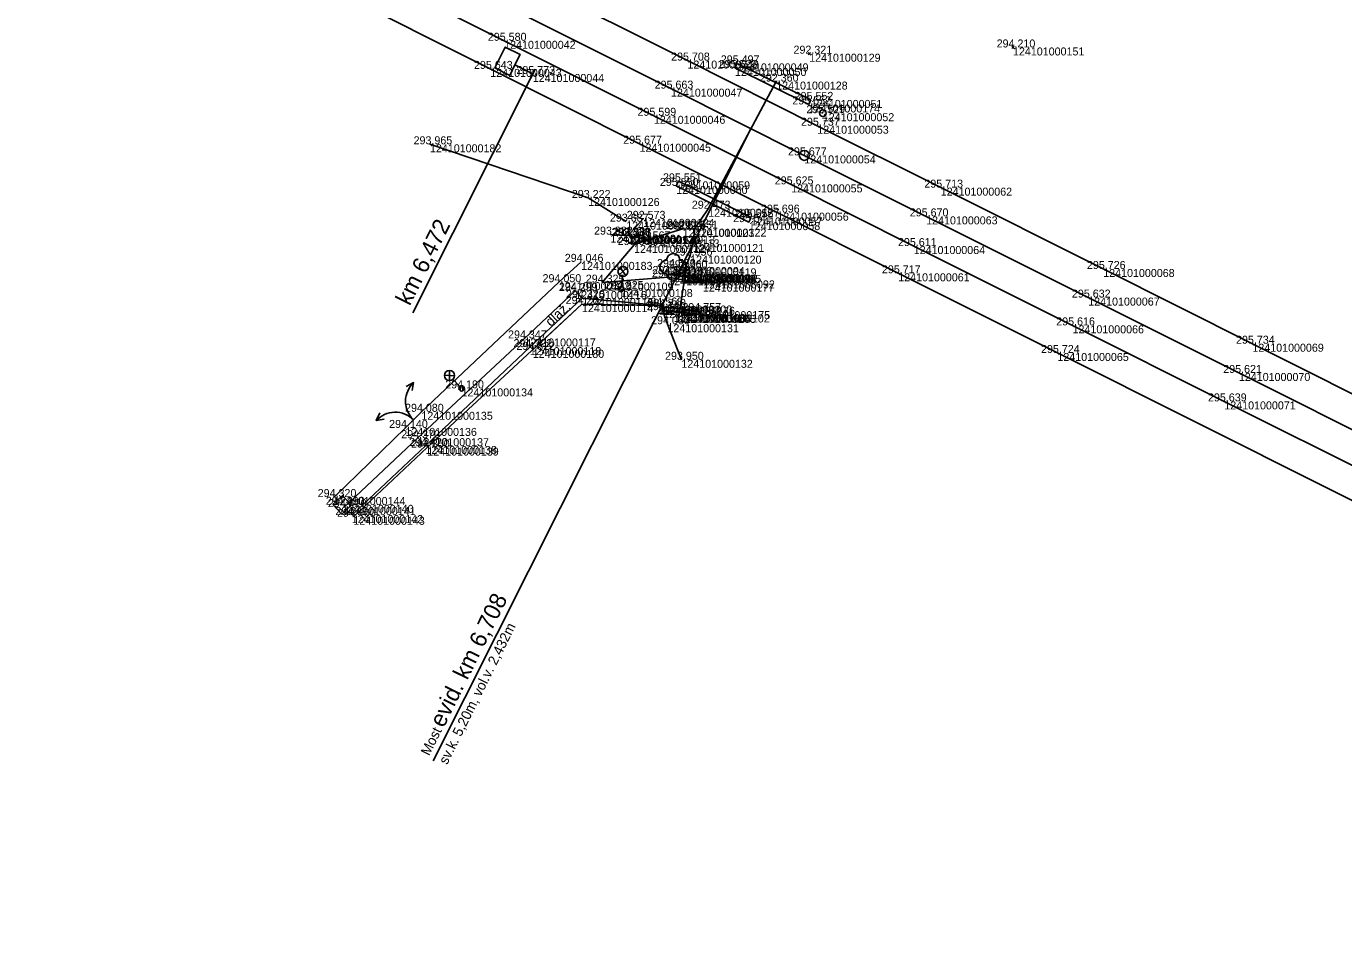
# Model space of a CAD drawing. Extents: x -616949 to -607976, y -1164436 to -1159224.
# Drawn here: x -613176.1 to -612978.5, y -1161728 to -1161592 of the extents above; entities that cross this region are included whole.
import ezdxf

# ---------------------------------------------------------------- set-up
doc = ezdxf.new("R2010")
doc.units = 0
for name, color, linetype in [('Vrstva 1', 7, 'Continuous'), ('Vrstva 16', 7, 'Continuous'), ('Vrstva 17', 7, 'Continuous'), ('Vrstva 18', 7, 'Continuous'), ('Vrstva 19', 7, 'Continuous'), ('Vrstva 25', 7, 'Continuous'), ('Vrstva 47', 7, 'Continuous'), ('Vrstva 49', 7, 'Continuous'), ('Vrstva 50', 7, 'Continuous'), ('Vrstva 51', 7, 'Continuous'), ('Vrstva 60', 7, 'Continuous'), ('Vrstva 61', 7, 'Continuous'), ('Vrstva 7', 7, 'Continuous')]:
    doc.layers.add(name, color=color, linetype=linetype)

msp = doc.modelspace()

# ---------------------------------------------------------------- linework, layer by layer
at = {"layer": 'Vrstva 1'}
for points in [[(-612836.3, -1161723.7), (-612837.64, -1161723.01), (-612851, -1161716.12), (-612864.8, -1161706.96), (-612874.11, -1161700.74), (-612883.8, -1161694.67), (-612893.99, -1161688.92), (-612900.94, -1161685.35), (-612902.32, -1161684.67), (-612923.96, -1161673.82), (-612946.7, -1161662.43), (-612968.71, -1161651.4), (-612992.18, -1161639.63), (-613014.55, -1161628.42), (-613038.93, -1161616.22), (-613057.44, -1161606.93), (-613076.92, -1161597.16), (-613100.26, -1161585.47), (-613122.66, -1161574.25), (-613146.78, -1161562.2), (-613166.98, -1161552.11), (-613189.63, -1161540.79)], [(-612836.3, -1161723.7), (-612837.64, -1161723.01), (-612851, -1161716.12), (-612865.7, -1161708.54), (-612879.87, -1161701.29), (-612896.11, -1161693.08), (-612897.16, -1161692.56), (-612899.6, -1161691.36), (-612902.62, -1161689.84), (-612904.01, -1161689.16), (-612926.34, -1161677.97), (-612949.01, -1161666.64), (-612970.85, -1161655.69), (-612994.2, -1161644.02), (-613016.8, -1161632.71), (-613041.11, -1161620.53), (-613059.39, -1161611.38), (-613079.39, -1161601.37), (-613102.4, -1161589.86), (-613124.84, -1161578.63), (-613149.33, -1161566.38), (-613169.01, -1161556.54), (-613191.83, -1161545.12)], [(-612838.4, -1161727.97), (-612839.52, -1161727.39), (-612849.62, -1161722.19), (-612861.87, -1161715.89), (-612876.82, -1161708.21), (-612890.37, -1161701.36), (-612894.8, -1161699.12), (-612896.29, -1161698.37), (-612899.37, -1161696.83), (-612901.81, -1161695.62), (-612928.78, -1161682.13), (-612951.31, -1161670.85), (-612973.15, -1161659.9), (-612996.39, -1161648.28), (-613019.15, -1161636.88), (-613042.98, -1161624.98), (-613061.36, -1161615.73), (-613081.95, -1161605.44), (-613104.41, -1161594.19), (-613127.64, -1161582.55), (-613152.33, -1161570.2), (-613170.83, -1161560.95), (-613193.86, -1161549.42)], [(-612838.4, -1161727.97), (-612839.52, -1161727.39), (-612849.62, -1161722.19), (-612862.62, -1161717.56), (-612874.04, -1161713.43), (-612884.82, -1161709.14), (-612890.21, -1161706.69), (-612892.64, -1161705.54), (-612895.15, -1161704.3), (-612918.74, -1161692.45), (-613021.43, -1161641.02), (-613045.3, -1161629.07), (-613063.44, -1161619.97), (-613084.1, -1161609.63), (-613106.49, -1161598.41), (-613129.98, -1161586.61), (-613154.55, -1161574.23)]]:
    msp.add_lwpolyline(points, dxfattribs=at)
at = {"layer": 'Vrstva 16'}
for points in [[(-613128.4, -1161664.14), (-613117.4, -1161653.8), (-613101.38, -1161638.84)], [(-613100.56, -1161640.14), (-613116.22, -1161654.97), (-613127.28, -1161665.33)]]:
    msp.add_lwpolyline(points, dxfattribs=at)
at = {"layer": 'Vrstva 17'}
for p, q in [((-613092.87, -1161627.35), (-613096.2, -1161630.4)), ((-613096.2, -1161630.4), (-613116.83, -1161649.84)), ((-613100.12, -1161640.55), (-613092.74, -1161633.68)), ((-613092.74, -1161633.68), (-613080.92, -1161633.9)), ((-613080.92, -1161633.9), (-613079.92, -1161636.71)), ((-613079.92, -1161636.71), (-613077.83, -1161642.04)), ((-613116.83, -1161649.84), (-613119.22, -1161652.26)), ((-613119.22, -1161652.26), (-613129.93, -1161662.63))]:
    msp.add_line(p, q, dxfattribs=at)
for points in [[(-613127.03, -1161665.59), (-613115.94, -1161655.21), (-613092.74, -1161633.68)], [(-613119.12, -1161646.04), (-613117.99, -1161645.46), (-613118.19, -1161646.67)], [(-613123.05, -1161650.02), (-613123.61, -1161651.16), (-613122.41, -1161650.94)]]:
    msp.add_lwpolyline(points, dxfattribs=at)
for centre, start, end in [((-613115.38, -1161648.27), 132.8722, 226.3921), ((-613120.77, -1161653.73), 44.3226, 137.8425)]:
    msp.add_arc(centre, 3.83, start, end, dxfattribs=at)
at = {"layer": 'Vrstva 18'}
for p, q in [((-613058.73, -1161603.74), (-613069.79, -1161598.27)), ((-613058.73, -1161603.74), (-613058.39, -1161603.06)), ((-613067.39, -1161607.38), (-613115.05, -1161702.21))]:
    msp.add_line(p, q, dxfattribs=at)
for points in [[(-613069.79, -1161598.27), (-613069.47, -1161597.58), (-613058.39, -1161603.06)], [(-613067.37, -1161620.69), (-613078.24, -1161615.27), (-613078.61, -1161615.96), (-613067.71, -1161621.39), (-613067.37, -1161620.69)]]:
    msp.add_lwpolyline(points, dxfattribs=at)
at = {"layer": 'Vrstva 19'}
for p, q in [((-613063.6, -1161600.31), (-613073.81, -1161619.38)), ((-613079.8, -1161629.67), (-613079.71, -1161629.18)), ((-613074.61, -1161630.62), (-613079.8, -1161629.67)), ((-613074.52, -1161630.13), (-613079.71, -1161629.18)), ((-613078.15, -1161629.2), (-613079.71, -1161629.18)), ((-613078.16, -1161635.26), (-613077.24, -1161629.26)), ((-613074.52, -1161630.13), (-613076.57, -1161629.3)), ((-613074.61, -1161630.62), (-613074.52, -1161630.13)), ((-613080.56, -1161634.59), (-613080.5, -1161634.1)), ((-613075.29, -1161635.24), (-613080.56, -1161634.59)), ((-613080.56, -1161634.59), (-613078.94, -1161635.16)), ((-613075.23, -1161634.74), (-613080.5, -1161634.1)), ((-613077.34, -1161635.31), (-613075.29, -1161635.24)), ((-613075.29, -1161635.24), (-613075.23, -1161634.74))]:
    msp.add_line(p, q, dxfattribs=at)
at = {"layer": 'Vrstva 25'}
for p, q in [((-613087.14, -1161629.3), (-613086.04, -1161628.28)), ((-613087.03, -1161628.19), (-613086.14, -1161629.39)), ((-613086.66, -1161629.54), (-613086.8, -1161631.03)), ((-613087.23, -1161631.47), (-613086.72, -1161631.05)), ((-613087, -1161631.79), (-613086.45, -1161631.34)), ((-613112.6, -1161645.15), (-613112.63, -1161643.65)), ((-613113.36, -1161644.33), (-613111.86, -1161644.46)), ((-613112.1, -1161644.94), (-613111.07, -1161646.04)), ((-613111.03, -1161646.65), (-613111.01, -1161645.99)), ((-613110.63, -1161646.69), (-613110.61, -1161645.98))]:
    msp.add_line(p, q, dxfattribs=at)
for centre, radius in [((-613086.59, -1161628.79), 0.749), ((-613086.84, -1161631.43), 0.4), ((-613112.61, -1161644.4), 0.749), ((-613110.8, -1161646.33), 0.4)]:
    msp.add_circle(centre, radius, dxfattribs=at)
at = {"layer": 'Vrstva 47'}
msp.add_lwpolyline([(-613130.12, -1161663.75), (-613128.67, -1161662.38), (-613127.3, -1161663.83), (-613128.75, -1161665.2), (-613130.12, -1161663.75)], dxfattribs=at)
at = {"layer": 'Vrstva 49'}
for p, q in [((-613058.83, -1161595.95), (-613058.48, -1161596.31)), ((-613058.83, -1161596.31), (-613058.48, -1161595.95)), ((-613028.27, -1161595.01), (-613027.91, -1161595.37)), ((-613028.27, -1161595.37), (-613027.91, -1161595.01)), ((-613085.8, -1161623.42), (-613083.57, -1161620.9)), ((-613088.48, -1161623.27), (-613085.68, -1161623.47)), ((-613085.68, -1161623.47), (-613082.82, -1161623.98)), ((-613082.82, -1161623.98), (-613077.62, -1161622.4)), ((-613079.8, -1161629.67), (-613089.72, -1161630.47))]:
    msp.add_line(p, q, dxfattribs=at)
for points in [[(-613086.1, -1161621.32), (-613091.81, -1161617.77), (-613115.54, -1161609.72)], [(-613077.24, -1161629.26), (-613077.27, -1161628.32), (-613076.52, -1161626.42), (-613076.13, -1161624.67), (-613075.79, -1161622.37), (-613073.81, -1161619.38)], [(-613089.72, -1161630.47), (-613084.93, -1161624.82), (-613082.82, -1161623.98)]]:
    msp.add_lwpolyline(points, dxfattribs=at)
at = {"layer": 'Vrstva 50'}
msp.add_line((-613079.1, -1161628.13), (-613078.96, -1161628.13), dxfattribs=at)
for centre, start, end in [((-613080.04, -1161628.12), 90, 270), ((-613079.04, -1161627.12), 0, 180), ((-613078.04, -1161628.12), 270, 90), ((-613079.04, -1161629.12), 180, 0)]:
    msp.add_arc(centre, 1, start, end, dxfattribs=at)
at = {"layer": 'Vrstva 51'}
msp.add_line((-613089.72, -1161630.47), (-613079.8, -1161629.67), dxfattribs=at)
for points in [[(-613101.38, -1161638.84), (-613093.75, -1161631.72), (-613092.7, -1161632.78), (-613100.56, -1161640.14)], [(-613092.7, -1161632.78), (-613080.92, -1161633.9), (-613080.5, -1161634.1)]]:
    msp.add_lwpolyline(points, dxfattribs=at)
at = {"layer": 'Vrstva 60'}
for p, q in [((-613104.41, -1161594.19), (-613104.41, -1161594.19)), ((-613058.66, -1161596.13), (-613058.66, -1161596.13)), ((-613028.09, -1161595.19), (-613028.09, -1161595.19)), ((-613076.92, -1161597.16), (-613076.92, -1161597.16)), ((-613069.79, -1161598.27), (-613069.79, -1161598.27)), ((-613069.47, -1161597.58), (-613069.47, -1161597.58)), ((-613106.49, -1161598.41), (-613106.49, -1161598.41)), ((-613100.12, -1161599.17), (-613100.12, -1161599.17)), ((-613079.39, -1161601.37), (-613079.39, -1161601.37)), ((-613063.6, -1161600.31), (-613063.6, -1161600.31)), ((-613058.73, -1161603.74), (-613058.73, -1161603.74)), ((-613058.39, -1161603.06), (-613058.39, -1161603.06)), ((-613081.95, -1161605.44), (-613081.95, -1161605.44)), ((-613056.61, -1161605.05), (-613056.61, -1161605.05)), ((-613057.44, -1161606.93), (-613057.44, -1161606.93)), ((-613115.54, -1161609.72), (-613115.54, -1161609.72)), ((-613084.1, -1161609.63), (-613084.1, -1161609.63)), ((-613059.39, -1161611.38), (-613059.39, -1161611.38)), ((-613078.61, -1161615.96), (-613078.61, -1161615.96)), ((-613078.24, -1161615.27), (-613078.24, -1161615.27)), ((-613061.36, -1161615.73), (-613061.36, -1161615.73)), ((-613091.81, -1161617.77), (-613091.81, -1161617.77)), ((-613038.93, -1161616.22), (-613038.93, -1161616.22)), ((-613073.81, -1161619.38), (-613073.81, -1161619.38)), ((-613063.44, -1161619.97), (-613063.44, -1161619.97)), ((-613086.1, -1161621.32), (-613086.1, -1161621.32)), ((-613083.57, -1161620.9), (-613083.57, -1161620.9)), ((-613067.71, -1161621.39), (-613067.71, -1161621.39)), ((-613067.37, -1161620.69), (-613067.37, -1161620.69)), ((-613041.11, -1161620.53), (-613041.11, -1161620.53)), ((-613088.48, -1161623.27), (-613088.48, -1161623.27)), ((-613085.85, -1161623.46), (-613085.85, -1161623.46)), ((-613085.8, -1161623.42), (-613085.8, -1161623.42)), ((-613085.68, -1161623.47), (-613085.68, -1161623.47)), ((-613082.82, -1161623.98), (-613082.82, -1161623.98)), ((-613077.62, -1161622.4), (-613077.62, -1161622.4)), ((-613075.79, -1161622.37), (-613075.79, -1161622.37)), ((-613084.93, -1161624.82), (-613084.93, -1161624.82)), ((-613076.13, -1161624.67), (-613076.13, -1161624.67)), ((-613042.98, -1161624.98), (-613042.98, -1161624.98)), ((-613092.87, -1161627.35), (-613092.87, -1161627.35)), ((-613076.52, -1161626.42), (-613076.52, -1161626.42)), ((-613079.8, -1161629.67), (-613079.8, -1161629.67)), ((-613079.71, -1161629.18), (-613079.71, -1161629.18)), ((-613079.03, -1161628.13), (-613079.03, -1161628.13)), ((-613078.15, -1161629.2), (-613078.15, -1161629.2)), ((-613077.67, -1161629.37), (-613077.67, -1161629.37)), ((-613077.31, -1161629.43), (-613077.31, -1161629.43)), ((-613077.27, -1161628.32), (-613077.27, -1161628.32)), ((-613077.24, -1161629.26), (-613077.24, -1161629.26)), ((-613076.57, -1161629.3), (-613076.57, -1161629.3)), ((-613045.3, -1161629.07), (-613045.3, -1161629.07)), ((-613014.55, -1161628.42), (-613014.55, -1161628.42)), ((-613096.2, -1161630.4), (-613096.2, -1161630.4)), ((-613093.75, -1161631.72), (-613093.75, -1161631.72)), ((-613089.72, -1161630.47), (-613089.72, -1161630.47)), ((-613086.84, -1161631.43), (-613086.84, -1161631.43)), ((-613074.61, -1161630.62), (-613074.61, -1161630.62)), ((-613074.52, -1161630.13), (-613074.52, -1161630.13)), ((-613092.74, -1161633.68), (-613092.74, -1161633.68)), ((-613092.7, -1161632.78), (-613092.7, -1161632.78)), ((-613016.8, -1161632.71), (-613016.8, -1161632.71)), ((-613080.92, -1161633.9), (-613080.92, -1161633.9)), ((-613080.56, -1161634.59), (-613080.56, -1161634.59)), ((-613080.5, -1161634.1), (-613080.5, -1161634.1)), ((-613078.94, -1161635.16), (-613078.94, -1161635.16)), ((-613078.73, -1161635.27), (-613078.73, -1161635.27)), ((-613078.18, -1161635.28), (-613078.18, -1161635.28)), ((-613078.16, -1161635.26), (-613078.16, -1161635.26)), ((-613077.34, -1161635.31), (-613077.34, -1161635.31)), ((-613075.29, -1161635.24), (-613075.29, -1161635.24)), ((-613075.23, -1161634.74), (-613075.23, -1161634.74)), ((-613079.92, -1161636.71), (-613079.92, -1161636.71)), ((-613019.15, -1161636.88), (-613019.15, -1161636.88)), ((-613101.38, -1161638.84), (-613101.38, -1161638.84)), ((-612992.18, -1161639.63), (-612992.18, -1161639.63)), ((-613100.56, -1161640.14), (-613100.56, -1161640.14)), ((-613100.12, -1161640.55), (-613100.12, -1161640.55)), ((-613021.43, -1161641.02), (-613021.43, -1161641.02)), ((-613077.83, -1161642.04), (-613077.83, -1161642.04)), ((-612994.2, -1161644.02), (-612994.2, -1161644.02)), ((-613110.8, -1161646.33), (-613110.8, -1161646.33)), ((-612996.39, -1161648.28), (-612996.39, -1161648.28)), ((-613116.83, -1161649.84), (-613116.83, -1161649.84)), ((-613119.22, -1161652.26), (-613119.22, -1161652.26)), ((-613117.4, -1161653.8), (-613117.4, -1161653.8)), ((-613116.22, -1161654.97), (-613116.22, -1161654.97)), ((-613115.94, -1161655.21), (-613115.94, -1161655.21)), ((-613129.93, -1161662.63), (-613129.93, -1161662.63)), ((-613128.71, -1161663.79), (-613128.71, -1161663.79)), ((-613128.4, -1161664.14), (-613128.4, -1161664.14)), ((-613127.28, -1161665.33), (-613127.28, -1161665.33)), ((-613127.03, -1161665.59), (-613127.03, -1161665.59))]:
    msp.add_line(p, q, dxfattribs=at)
at = {"layer": 'Vrstva 7'}
for p, q in [((-613100.12, -1161599.17), (-613118.1, -1161635)), ((-613100.45, -1161599.84), (-613099.78, -1161598.5)), ((-613056.57, -1161605.07), (-613056.66, -1161605.02))]:
    msp.add_line(p, q, dxfattribs=at)
msp.add_lwpolyline([(-613100.12, -1161599.17), (-613102.8, -1161597.82), (-613102.01, -1161596.26), (-613104.25, -1161595.14), (-613105.82, -1161598.27), (-613103.58, -1161599.39), (-613102.8, -1161597.82)], dxfattribs=at)
for centre, radius in [((-613056.61, -1161605.05), 0.5), ((-613059.39, -1161611.38), 0.75)]:
    msp.add_circle(centre, radius, dxfattribs=at)

# ---------------------------------------------------------------- texts
at = {"layer": 'Vrstva 18'}
for s, height, p in [('evid. km 6,708', 2.5, (-613113.49, -1161697.36)), ('sv.k. 5,20m, vol.v. 2,432m', 1.5, (-613112.97, -1161702.86)), ('Most', 1.5, (-613115.66, -1161701.53))]:
    msp.add_text(s, height=height, rotation=63.6863, dxfattribs=at).set_placement(p)
at = {"layer": 'Vrstva 51'}
msp.add_text('dlaž.', height=1.5, rotation=43.1221, dxfattribs=at).set_placement((-613097.4, -1161637.16))
at = {"layer": 'Vrstva 60'}
for s, p in [('124101000042', (-613104.41, -1161595.39)), ('124101000129', (-613058.66, -1161597.33)), ('124101000151', (-613028.09, -1161596.39)), ('124101000048', (-613076.92, -1161598.36)), ('124101000050', (-613069.79, -1161599.47)), ('124101000049', (-613069.47, -1161598.78)), ('124101000043', (-613106.49, -1161599.61)), ('124101000044', (-613100.12, -1161600.37)), ('124101000047', (-613079.39, -1161602.57)), ('124101000128', (-613063.6, -1161601.51)), ('124101000174', (-613058.73, -1161604.94)), ('124101000051', (-613058.39, -1161604.26)), ('124101000046', (-613081.95, -1161606.64)), ('124101000052', (-613056.61, -1161606.25)), ('124101000053', (-613057.44, -1161608.13)), ('124101000182', (-613115.54, -1161610.92)), ('124101000045', (-613084.1, -1161610.83)), ('124101000054', (-613059.39, -1161612.58)), ('124101000060', (-613078.61, -1161617.16)), ('124101000059', (-613078.24, -1161616.47)), ('124101000055', (-613061.36, -1161616.93)), ('124101000126', (-613091.81, -1161618.97)), ('124101000062', (-613038.93, -1161617.42)), ('124101000127', (-613073.81, -1161620.58)), ('124101000056', (-613063.44, -1161621.17)), ('124101000111', (-613086.1, -1161622.52)), ('124101000124', (-613083.57, -1161622.1)), ('124101000058', (-613067.71, -1161622.59)), ('124101000057', (-613067.37, -1161621.89)), ('124101000063', (-613041.11, -1161621.73)), ('124101000181', (-613088.48, -1161624.47)), ('124101000179', (-613085.85, -1161624.66)), ('124101000125', (-613085.8, -1161624.62)), ('124101000110', (-613085.68, -1161624.67)), ('124101000113', (-613082.82, -1161625.18)), ('124101000123', (-613077.62, -1161623.6)), ('124101000122', (-613075.79, -1161623.57)), ('124101000112', (-613084.93, -1161626.02)), ('124101000121', (-613076.13, -1161625.87)), ('124101000064', (-613042.98, -1161626.18)), ('124101000183', (-613092.87, -1161628.55)), ('124101000120', (-613076.52, -1161627.62)), ('124101000178', (-613079.8, -1161630.87)), ('124101000093', (-613079.71, -1161630.38)), ('124101000094', (-613079.03, -1161629.33)), ('124101000097', (-613078.15, -1161630.4)), ('124101000099', (-613077.67, -1161630.57)), ('124101000098', (-613077.31, -1161630.63)), ('124101000119', (-613077.27, -1161629.52)), ('124101000096', (-613077.24, -1161630.46)), ('124101000095', (-613076.57, -1161630.5)), ('124101000061', (-613045.3, -1161630.27)), ('124101000068', (-613014.55, -1161629.62)), ('124101000133', (-613096.2, -1161631.6)), ('124101000116', (-613093.75, -1161632.92)), ('124101000109', (-613089.72, -1161631.67)), ('124101000108', (-613086.84, -1161632.63)), ('124101000177', (-613074.61, -1161631.82)), ('124101000092', (-613074.52, -1161631.33)), ('124101000114', (-613092.74, -1161634.88)), ('124101000115', (-613092.7, -1161633.98)), ('124101000067', (-613016.8, -1161633.91)), ('124101000100', (-613080.92, -1161635.1)), ('124101000101', (-613080.56, -1161635.79)), ('124101000176', (-613080.5, -1161635.3)), ('124101000103', (-613078.94, -1161636.36)), ('124101000107', (-613078.73, -1161636.47)), ('124101000106', (-613078.18, -1161636.48)), ('124101000104', (-613078.16, -1161636.46)), ('124101000105', (-613077.34, -1161636.51)), ('124101000102', (-613075.29, -1161636.44)), ('124101000175', (-613075.23, -1161635.94)), ('124101000131', (-613079.92, -1161637.91)), ('124101000066', (-613019.15, -1161638.07)), ('124101000117', (-613101.38, -1161640.04)), ('124101000069', (-612992.18, -1161640.83)), ('124101000118', (-613100.56, -1161641.34)), ('124101000180', (-613100.12, -1161641.75)), ('124101000065', (-613021.43, -1161642.22)), ('124101000132', (-613077.83, -1161643.24)), ('124101000070', (-612994.2, -1161645.22)), ('124101000134', (-613110.8, -1161647.53)), ('124101000071', (-612996.39, -1161649.48)), ('124101000135', (-613116.83, -1161651.04)), ('124101000136', (-613119.22, -1161653.46)), ('124101000137', (-613117.4, -1161655)), ('124101000138', (-613116.22, -1161656.17)), ('124101000139', (-613115.94, -1161656.41)), ('124101000144', (-613129.93, -1161663.83)), ('124101000140', (-613128.71, -1161664.99)), ('124101000141', (-613128.4, -1161665.34)), ('124101000142', (-613127.28, -1161666.53)), ('124101000143', (-613127.03, -1161666.79))]:
    msp.add_text(s, height=1.2, dxfattribs=at).set_placement(p)
at = {"layer": 'Vrstva 61'}
for s, p in [('295.580', (-613106.86, -1161594.19)), ('294.210', (-613030.54, -1161595.19)), ('295.708', (-613079.37, -1161597.16)), ('292.321', (-613061.01, -1161596.13)), ('295.643', (-613108.94, -1161598.41)), ('295.773', (-613102.57, -1161599.17)), ('295.523', (-613072.24, -1161598.27)), ('295.497', (-613071.92, -1161597.58)), ('295.663', (-613081.84, -1161601.37)), ('292.360', (-613066.05, -1161600.31)), ('295.552', (-613060.84, -1161603.06)), ('295.599', (-613084.41, -1161605.44)), ('295.552', (-613061.18, -1161603.74)), ('295.529', (-613059.07, -1161605.05)), ('295.737', (-613059.89, -1161606.93)), ('293.965', (-613118, -1161609.72)), ('295.677', (-613086.55, -1161609.63)), ('295.677', (-613061.84, -1161611.38)), ('295.551', (-613080.59, -1161615.27)), ('295.550', (-613081.06, -1161615.96)), ('295.625', (-613063.82, -1161615.73)), ('295.713', (-613041.38, -1161616.22)), ('293.222', (-613094.26, -1161617.77)), ('292.573', (-613086.02, -1161620.9)), ('292.473', (-613076.26, -1161619.38)), ('295.555', (-613069.83, -1161620.69)), ('295.696', (-613065.89, -1161619.97)), ('295.670', (-613043.57, -1161620.53)), ('293.687', (-613088.55, -1161621.32)), ('292.549', (-613080.07, -1161622.4)), ('292.551', (-613078.14, -1161622.37)), ('295.541', (-613070.07, -1161621.39)), ('293.982', (-613090.93, -1161623.27)), ('293.330', (-613088.3, -1161623.46)), ('292.581', (-613088.15, -1161623.42)), ('293.238', (-613088.13, -1161623.47)), ('293.630', (-613087.38, -1161624.82)), ('293.567', (-613085.27, -1161623.98)), ('292.913', (-613078.58, -1161624.67)), ('295.611', (-613045.34, -1161624.98)), ('292.956', (-613078.97, -1161626.42)), ('294.046', (-613095.32, -1161627.35)), ('294.563', (-613081.48, -1161628.13)), ('292.960', (-613079.72, -1161628.32)), ('295.717', (-613047.75, -1161629.07)), ('295.726', (-613017, -1161628.42)), ('294.050', (-613098.65, -1161630.4)), ('294.325', (-613092.17, -1161630.47)), ('294.583', (-613082.25, -1161629.67)), ('294.583', (-613082.16, -1161629.18)), ('293.299', (-613080.6, -1161629.2)), ('293.418', (-613080.12, -1161629.37)), ('293.834', (-613079.76, -1161629.43)), ('292.906', (-613079.69, -1161629.26)), ('293.276', (-613079.02, -1161629.3)), ('294.755', (-613077.06, -1161630.62)), ('294.755', (-613076.97, -1161630.13)), ('294.299', (-613096.2, -1161631.72)), ('294.326', (-613095.15, -1161632.78)), ('294.325', (-613089.3, -1161631.43)), ('295.632', (-613019.25, -1161632.71)), ('294.262', (-613095.19, -1161633.68)), ('294.563', (-613083.37, -1161633.9)), ('294.740', (-613083.01, -1161634.59)), ('294.740', (-613082.95, -1161634.1)), ('294.757', (-613077.68, -1161634.74)), ('294.060', (-613082.37, -1161636.71)), ('293.430', (-613081.39, -1161635.16)), ('293.460', (-613081.18, -1161635.27)), ('294.012', (-613080.63, -1161635.28)), ('293.024', (-613080.61, -1161635.26)), ('293.440', (-613079.79, -1161635.31)), ('294.757', (-613077.74, -1161635.24)), ('295.616', (-613021.6, -1161636.88)), ('294.347', (-613103.83, -1161638.84)), ('294.322', (-613103.01, -1161640.14)), ('294.322', (-613102.57, -1161640.55)), ('295.734', (-612994.63, -1161639.63)), ('293.950', (-613080.28, -1161642.04)), ('295.724', (-613023.88, -1161641.02)), ('295.621', (-612996.55, -1161644.02)), ('294.190', (-613113.25, -1161646.33)), ('295.639', (-612998.84, -1161648.28)), ('294.080', (-613119.28, -1161649.84)), ('294.140', (-613121.67, -1161652.26)), ('294.370', (-613119.85, -1161653.8)), ('294.420', (-613118.67, -1161654.97)), ('294.350', (-613118.39, -1161655.21)), ('294.320', (-613132.38, -1161662.63)), ('294.390', (-613131.16, -1161663.79)), ('294.420', (-613130.85, -1161664.14)), ('294.490', (-613129.73, -1161665.33)), ('294.400', (-613129.48, -1161665.59))]:
    msp.add_text(s, height=1.2, dxfattribs=at).set_placement(p)
at = {"layer": 'Vrstva 7'}
msp.add_text('km 6,472', height=2.5, rotation=63.3817, dxfattribs=at).set_placement((-613118.58, -1161634.06))

doc.saveas('drawing.dxf')
